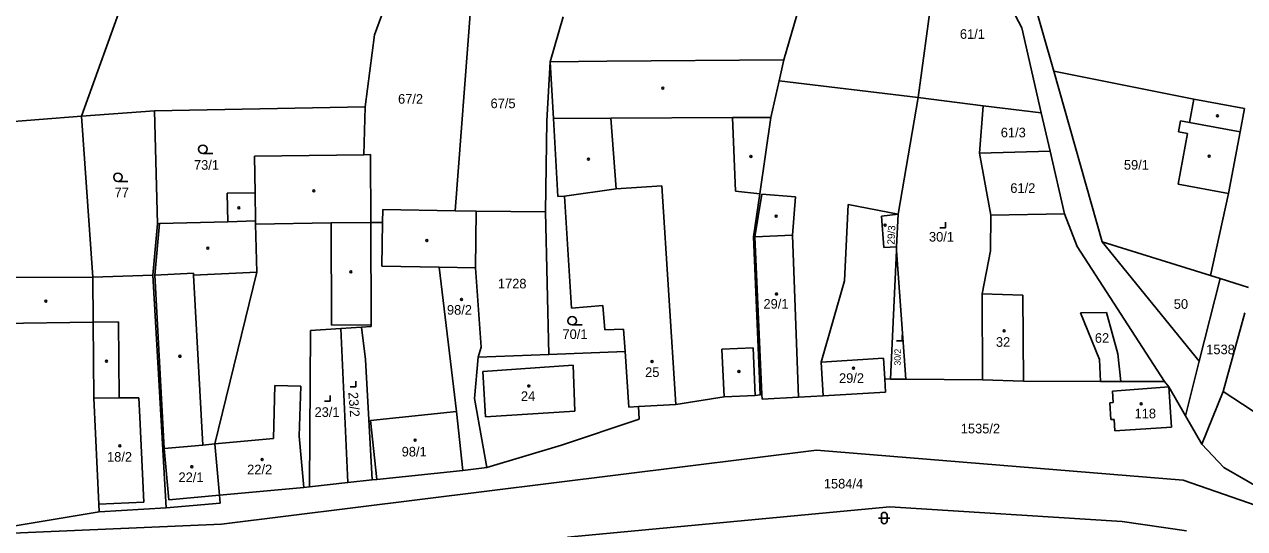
# Model space of a CAD drawing. Extents: x -801826 to -800592, y -1032871 to -1031813.
# Drawn here: x -801458.2 to -801242.3, y -1032295.9 to -1032206.7 of the extents above; entities that cross this region are included whole.
import ezdxf

# ---------------------------------------------------------------- set-up
doc = ezdxf.new("R2010")
doc.units = 0
for name, color, linetype in [('Vrstva 1', 7, 'Continuous'), ('Vrstva 18', 7, 'Continuous'), ('Vrstva 19', 7, 'Continuous'), ('Vrstva 25', 7, 'Continuous'), ('Vrstva 4', 7, 'Continuous')]:
    doc.layers.add(name, color=color, linetype=linetype)

msp = doc.modelspace()

# ---------------------------------------------------------------- linework, layer by layer
at = {"layer": 'Vrstva 1'}
for p, q in [((-801448.05, -1032222.93), (-801416.74, -1032135.73)), ((-801448.05, -1032222.93), (-801416.74, -1032135.73)), ((-801316.77, -1032188.79), (-801323.85, -1032212.97)), ((-801296.17, -1032190.86), (-801300.07, -1032219.68)), ((-801281.75, -1032207.34), (-801287.23, -1032196.91)), ((-801276.11, -1032214.97), (-801280.45, -1032199.73)), ((-801396.23, -1032208.59), (-801393.66, -1032201.6)), ((-801393.66, -1032201.6), (-801396.23, -1032208.59)), ((-801381.98, -1032239.7), (-801379.18, -1032203.38)), ((-801381.98, -1032239.7), (-801379.18, -1032203.38)), ((-801379.18, -1032203.38), (-801381.98, -1032239.7)), ((-801365.14, -1032213.36), (-801362.89, -1032205.37)), ((-801365.14, -1032213.36), (-801362.89, -1032205.37)), ((-801397.89, -1032221.33), (-801396.23, -1032208.59)), ((-801396.23, -1032208.59), (-801397.89, -1032221.33)), ((-801278.3, -1032222.36), (-801281.75, -1032207.34)), ((-801323.85, -1032212.97), (-801355.17, -1032213.25)), ((-801323.85, -1032212.97), (-801324.69, -1032216.69)), ((-801365.77, -1032223.78), (-801365.14, -1032213.36)), ((-801365.77, -1032223.78), (-801365.14, -1032213.36)), ((-801355.17, -1032213.25), (-801365.14, -1032213.36)), ((-801364.57, -1032223.37), (-801365.14, -1032213.36)), ((-801267.55, -1032245.2), (-801276.11, -1032214.97)), ((-801276.11, -1032214.97), (-801251.32, -1032219.94)), ((-801324.69, -1032216.69), (-801326.16, -1032223.18)), ((-801300.07, -1032219.68), (-801324.69, -1032216.69)), ((-801435.15, -1032222.03), (-801397.89, -1032221.33)), ((-801397.89, -1032221.33), (-801398.12, -1032229.78)), ((-801397.89, -1032221.33), (-801398.12, -1032229.78)), ((-801303.62, -1032240.3), (-801300.07, -1032219.68)), ((-801300.07, -1032219.68), (-801288.59, -1032221.1)), ((-801289.22, -1032229.47), (-801288.59, -1032221.1)), ((-801288.59, -1032221.1), (-801278.3, -1032222.36)), ((-801252.09, -1032224.07), (-801251.32, -1032219.94)), ((-801474.72, -1032225.02), (-801448.05, -1032222.93)), ((-801474.72, -1032225.02), (-801448.05, -1032222.93)), ((-801448.05, -1032222.93), (-801435.15, -1032222.03)), ((-801446.08, -1032251.42), (-801448.05, -1032222.93)), ((-801434.6, -1032241.97), (-801435.15, -1032222.03)), ((-801363.79, -1032237.15), (-801364.57, -1032223.37)), ((-801326.16, -1032223.18), (-801328.11, -1032236.71)), ((-801278.3, -1032222.36), (-801276.74, -1032229.12)), ((-801254.03, -1032225.74), (-801253.66, -1032223.77)), ((-801253.66, -1032223.77), (-801252.09, -1032224.07)), ((-801365.98, -1032239.9), (-801365.77, -1032223.78)), ((-801365.98, -1032239.9), (-801365.77, -1032223.78)), ((-801252.46, -1032226.03), (-801254.03, -1032225.74)), ((-801254.12, -1032234.98), (-801252.46, -1032226.03)), ((-801417.45, -1032230.02), (-801398.12, -1032229.78)), ((-801417.37, -1032236.53), (-801417.45, -1032230.02)), ((-801398.12, -1032229.78), (-801396.92, -1032229.76)), ((-801398.12, -1032229.78), (-801396.92, -1032229.76)), ((-801396.92, -1032229.76), (-801396.89, -1032241.78)), ((-801396.92, -1032229.76), (-801396.89, -1032241.78)), ((-801276.74, -1032229.12), (-801289.22, -1032229.47)), ((-801287.21, -1032240.47), (-801289.22, -1032229.47)), ((-801276.74, -1032229.12), (-801274.19, -1032240.25)), ((-801417.37, -1032236.53), (-801422.27, -1032236.59)), ((-801422.27, -1032236.59), (-801422.2, -1032241.63)), ((-801417.37, -1032236.53), (-801417.3, -1032241.49)), ((-801328.11, -1032236.71), (-801329.2, -1032244.28)), ((-801245.17, -1032236.64), (-801254.12, -1032234.98)), ((-801245.17, -1032236.64), (-801248.38, -1032251.15)), ((-801362.64, -1032237.08), (-801363.79, -1032237.15)), ((-801361.4, -1032256.92), (-801362.64, -1032237.08)), ((-801313.09, -1032252.05), (-801312.46, -1032238.57)), ((-801312.46, -1032238.57), (-801303.62, -1032240.3)), ((-801394.75, -1032239.44), (-801394.8, -1032241.77)), ((-801394.8, -1032241.77), (-801394.75, -1032239.44)), ((-801381.98, -1032239.7), (-801394.75, -1032239.44)), ((-801394.75, -1032239.44), (-801381.98, -1032239.7)), ((-801378.25, -1032239.77), (-801381.98, -1032239.7)), ((-801381.98, -1032239.7), (-801378.25, -1032239.77)), ((-801378.4, -1032249.79), (-801378.25, -1032239.77)), ((-801378.25, -1032239.77), (-801365.98, -1032239.9)), ((-801378.25, -1032239.77), (-801365.98, -1032239.9)), ((-801365.98, -1032239.9), (-801365.4, -1032265.08)), ((-801303.89, -1032246.07), (-801303.62, -1032240.3)), ((-801287.28, -1032246.76), (-801287.21, -1032240.47)), ((-801274.19, -1032240.25), (-801287.21, -1032240.47)), ((-801271.96, -1032246), (-801274.19, -1032240.25)), ((-801435.46, -1032251.09), (-801434.6, -1032241.97)), ((-801434.6, -1032241.97), (-801434.25, -1032241.96)), ((-801422.2, -1032241.63), (-801434.25, -1032241.96)), ((-801417.3, -1032241.49), (-801417.3, -1032242.04)), ((-801417.3, -1032242.04), (-801417.05, -1032250.54)), ((-801394.8, -1032241.77), (-801396.89, -1032241.78)), ((-801396.89, -1032241.78), (-801394.8, -1032241.77)), ((-801396.89, -1032241.78), (-801396.85, -1032259.87)), ((-801329.2, -1032244.28), (-801328, -1032272.21)), ((-801267.55, -1032245.2), (-801250.37, -1032266.27)), ((-801248.38, -1032251.15), (-801267.55, -1032245.2)), ((-801303.92, -1032246.72), (-801304.98, -1032269.44)), ((-801303.92, -1032246.72), (-801303.89, -1032246.07)), ((-801302.26, -1032269.46), (-801303.92, -1032246.72)), ((-801288.76, -1032254.36), (-801287.28, -1032246.76)), ((-801256.53, -1032269.9), (-801271.96, -1032246)), ((-801446.08, -1032251.42), (-801462.54, -1032251.48)), ((-801446.08, -1032251.42), (-801435.46, -1032251.09)), ((-801446.08, -1032251.42), (-801446.01, -1032259.36)), ((-801433.1, -1032292.23), (-801435.46, -1032251.09)), ((-801424.5, -1032280.92), (-801417.05, -1032250.54)), ((-801378.4, -1032249.79), (-801384.79, -1032249.68)), ((-801384.79, -1032249.68), (-801381.72, -1032275.18)), ((-801377.36, -1032263.81), (-801378.4, -1032249.79)), ((-801246.69, -1032251.67), (-801250.37, -1032266.27)), ((-801246.69, -1032251.67), (-801248.38, -1032251.15)), ((-801241.66, -1032253.23), (-801246.69, -1032251.67)), ((-801317.25, -1032266.46), (-801313.09, -1032252.05)), ((-801288.69, -1032269.58), (-801288.76, -1032254.36)), ((-801355.87, -1032256.41), (-801361.4, -1032256.92)), ((-801355.48, -1032260.74), (-801355.87, -1032256.41)), ((-801266.78, -1032257.67), (-801271.39, -1032257.72)), ((-801271.39, -1032257.72), (-801268.01, -1032266.01)), ((-801264.75, -1032265.01), (-801266.78, -1032257.67)), ((-801246.16, -1032271.65), (-801242.31, -1032257.72)), ((-801445.89, -1032272.81), (-801446.01, -1032259.36)), ((-801402.19, -1032260.49), (-801398.52, -1032260.27)), ((-801398.52, -1032260.27), (-801396.84, -1032260.13)), ((-801397.81, -1032265.98), (-801398.52, -1032260.27)), ((-801396.84, -1032260.13), (-801396.85, -1032259.87)), ((-801407.71, -1032288.51), (-801407.53, -1032260.84)), ((-801407.53, -1032260.84), (-801402.19, -1032260.49)), ((-801400.97, -1032287.76), (-801402.19, -1032260.49)), ((-801352.2, -1032260.61), (-801355.48, -1032260.74)), ((-801352.2, -1032260.61), (-801351.93, -1032264.58)), ((-801377.9, -1032265.55), (-801377.36, -1032263.81)), ((-801351.93, -1032264.58), (-801365.4, -1032265.08)), ((-801351.93, -1032264.58), (-801351.27, -1032274.41)), ((-801396.63, -1032287.28), (-801397.81, -1032265.98)), ((-801378.53, -1032272.86), (-801377.9, -1032265.55)), ((-801365.4, -1032265.08), (-801377.9, -1032265.55)), ((-801306.19, -1032265.76), (-801317.25, -1032266.46)), ((-801316.89, -1032272.41), (-801317.25, -1032266.46)), ((-801305.98, -1032269.43), (-801306.19, -1032265.76)), ((-801268.01, -1032266.01), (-801267.83, -1032269.86)), ((-801264.23, -1032269.88), (-801264.75, -1032265.01)), ((-801250.37, -1032266.27), (-801252.81, -1032275.94)), ((-801305.85, -1032271.76), (-801305.98, -1032269.43)), ((-801305.98, -1032269.43), (-801304.98, -1032269.44)), ((-801304.98, -1032269.44), (-801302.26, -1032269.46)), ((-801302.26, -1032269.46), (-801288.69, -1032269.58)), ((-801281.47, -1032269.82), (-801288.69, -1032269.58)), ((-801267.83, -1032269.86), (-801281.47, -1032269.82)), ((-801264.23, -1032269.88), (-801267.83, -1032269.86)), ((-801265.72, -1032271.58), (-801255.76, -1032270.84)), ((-801256.53, -1032269.9), (-801264.23, -1032269.88)), ((-801255.76, -1032270.84), (-801256.53, -1032269.9)), ((-801255.27, -1032277.97), (-801255.76, -1032270.84)), ((-801252.81, -1032275.94), (-801255.76, -1032270.84)), ((-801445, -1032291.59), (-801445.89, -1032272.81)), ((-801376.35, -1032285.06), (-801378.53, -1032272.86)), ((-801334.4, -1032272.57), (-801342.94, -1032273.94)), ((-801328.9, -1032272.32), (-801334.4, -1032272.57)), ((-801328.9, -1032272.32), (-801328, -1032272.21)), ((-801328, -1032272.21), (-801327.72, -1032272.18)), ((-801327.68, -1032272.98), (-801327.72, -1032272.18)), ((-801321.23, -1032272.63), (-801327.68, -1032272.98)), ((-801316.89, -1032272.41), (-801321.23, -1032272.63)), ((-801305.85, -1032271.76), (-801316.89, -1032272.41)), ((-801265.6, -1032273.58), (-801265.72, -1032271.58)), ((-801249.91, -1032280.96), (-801246.16, -1032271.65)), ((-801215.82, -1032291.6), (-801246.16, -1032271.65)), ((-801381.72, -1032275.18), (-801380.62, -1032285.59)), ((-801351.27, -1032274.41), (-801349.57, -1032274.31)), ((-801349.57, -1032274.31), (-801342.94, -1032273.94)), ((-801349.42, -1032276.55), (-801349.57, -1032274.31)), ((-801266.2, -1032273.62), (-801265.6, -1032273.58)), ((-801266.02, -1032276.62), (-801266.2, -1032273.62)), ((-801363.15, -1032281.14), (-801349.42, -1032276.55)), ((-801265.41, -1032276.59), (-801266.02, -1032276.62)), ((-801265.29, -1032278.59), (-801265.41, -1032276.59)), ((-801249.91, -1032280.96), (-801252.81, -1032275.94)), ((-801265.29, -1032278.59), (-801255.27, -1032277.97)), ((-801423.66, -1032289.99), (-801424.5, -1032280.92)), ((-801423.3, -1032295.08), (-801318.09, -1032281.99)), ((-801376.35, -1032285.06), (-801363.15, -1032281.14)), ((-801318.09, -1032281.99), (-801253.19, -1032287.31)), ((-801246.04, -1032285.11), (-801249.91, -1032280.96)), ((-801380.62, -1032285.59), (-801395.83, -1032287.2)), ((-801380.62, -1032285.59), (-801376.35, -1032285.06)), ((-801228.18, -1032295.28), (-801246.04, -1032285.11)), ((-801407.71, -1032288.51), (-801408.71, -1032288.6)), ((-801400.97, -1032287.76), (-801407.71, -1032288.51)), ((-801396.63, -1032287.28), (-801400.97, -1032287.76)), ((-801395.83, -1032287.2), (-801396.63, -1032287.28)), ((-801253.19, -1032287.31), (-801216.74, -1032299.98)), ((-801408.71, -1032288.6), (-801423.66, -1032289.99)), ((-801423.66, -1032289.99), (-801423.54, -1032291.4)), ((-801444.94, -1032292.94), (-801445, -1032291.59)), ((-801433.1, -1032292.23), (-801444.94, -1032292.94)), ((-801423.54, -1032291.4), (-801433.1, -1032292.23)), ((-801362.11, -1032297.43), (-801305.07, -1032292.01)), ((-801305.07, -1032292.01), (-801263.98, -1032294.66)), ((-801444.94, -1032292.94), (-801461.89, -1032295.77)), ((-801263.98, -1032294.66), (-801252.6, -1032296.27)), ((-801466.62, -1032296.97), (-801423.3, -1032295.08))]:
    msp.add_line(p, q, dxfattribs=at)
at = {"layer": 'Vrstva 25'}
for p, q in [((-801424.84, -1032229.56), (-801426.59, -1032229.56)), ((-801439.86, -1032234.51), (-801441.61, -1032234.51)), ((-801296.22, -1032242.69), (-801295.22, -1032242.69)), ((-801295.22, -1032242.69), (-801295.22, -1032241.69)), ((-801359.52, -1032259.88), (-801361.27, -1032259.88)), ((-801302.93, -1032262.68), (-801302.93, -1032261.68)), ((-801303.93, -1032262.68), (-801302.93, -1032262.68)), ((-801400.53, -1032270.83), (-801399.53, -1032270.83)), ((-801399.53, -1032270.83), (-801399.53, -1032269.83)), ((-801405.06, -1032273.36), (-801404.06, -1032273.36)), ((-801404.06, -1032273.36), (-801404.06, -1032272.36)), ((-801307.08, -1032294.02), (-801305.08, -1032294.02)), ((-801306.58, -1032294.52), (-801306.58, -1032293.52)), ((-801305.58, -1032294.52), (-801305.58, -1032293.52))]:
    msp.add_line(p, q, dxfattribs=at)
for centre, radius in [((-801345.26, -1032217.98), 0.175), ((-801247.15, -1032222.9), 0.175), ((-801426.59, -1032228.81), 0.75), ((-801329.65, -1032230.07), 0.175), ((-801248.61, -1032230.02), 0.175), ((-801358.4, -1032230.54), 0.175), ((-801441.61, -1032233.76), 0.75), ((-801406.98, -1032236.18), 0.175), ((-801420.22, -1032239.15), 0.175), ((-801325.2, -1032240.65), 0.175), ((-801305.94, -1032242.22), 0.175), ((-801386.98, -1032244.95), 0.175), ((-801425.72, -1032246.29), 0.175), ((-801400.41, -1032250.5), 0.175), ((-801454.35, -1032255.65), 0.175), ((-801380.83, -1032255.36), 0.175), ((-801325.14, -1032254.4), 0.175), ((-801361.27, -1032259.13), 0.75), ((-801284.89, -1032260.91), 0.175), ((-801443.64, -1032266.26), 0.175), ((-801430.64, -1032265.42), 0.175), ((-801347.15, -1032266.34), 0.175), ((-801331.77, -1032268.1), 0.175), ((-801311.52, -1032267.51), 0.175), ((-801368.96, -1032270.67), 0.175), ((-801260.62, -1032273.81), 0.175), ((-801441.28, -1032281.24), 0.175), ((-801389.06, -1032280.23), 0.175), ((-801416.11, -1032283.68), 0.175), ((-801428.55, -1032284.94), 0.175)]:
    msp.add_circle(centre, radius, dxfattribs=at)
for centre, start, end in [((-801306.08, -1032293.52), 0, 180), ((-801306.08, -1032294.52), 180, 0)]:
    msp.add_arc(centre, 0.5, start, end, dxfattribs=at)
at = {"layer": 'Vrstva 4'}
for p, q in [((-801251.32, -1032219.94), (-801242.38, -1032221.6)), ((-801242.38, -1032221.6), (-801243.14, -1032225.73)), ((-801354.41, -1032223.32), (-801364.57, -1032223.37)), ((-801354.41, -1032223.32), (-801332.91, -1032223.21)), ((-801353.51, -1032235.79), (-801354.41, -1032223.32)), ((-801332.91, -1032223.21), (-801326.16, -1032223.18)), ((-801332.91, -1032223.21), (-801332.38, -1032236.24)), ((-801243.14, -1032225.73), (-801252.09, -1032224.07)), ((-801243.14, -1032225.73), (-801245.17, -1032236.64)), ((-801353.51, -1032235.79), (-801362.64, -1032237.08)), ((-801345.43, -1032235.27), (-801353.51, -1032235.79)), ((-801342.94, -1032273.94), (-801345.43, -1032235.27)), ((-801332.38, -1032236.24), (-801328.11, -1032236.71)), ((-801328.95, -1032244.27), (-801327.71, -1032236.75)), ((-801327.71, -1032236.75), (-801321.77, -1032237.23)), ((-801322.31, -1032244), (-801321.77, -1032237.23)), ((-801303.62, -1032240.3), (-801306.56, -1032240.63)), ((-801306.56, -1032240.63), (-801306.18, -1032246.15)), ((-801435.11, -1032251.08), (-801434.25, -1032241.96)), ((-801422.2, -1032241.63), (-801417.3, -1032241.49)), ((-801403.91, -1032241.8), (-801417.3, -1032242.04)), ((-801396.89, -1032241.78), (-801403.91, -1032241.8)), ((-801403.91, -1032241.8), (-801403.86, -1032259.89)), ((-801394.95, -1032249.5), (-801394.8, -1032241.77)), ((-801328.95, -1032244.27), (-801322.31, -1032244)), ((-801327.72, -1032272.18), (-801328.95, -1032244.27)), ((-801321.23, -1032272.63), (-801322.31, -1032244)), ((-801306.18, -1032246.15), (-801303.89, -1032246.07)), ((-801384.79, -1032249.68), (-801394.95, -1032249.5)), ((-801428.27, -1032250.7), (-801435.11, -1032251.08)), ((-801433.44, -1032281.75), (-801435.11, -1032251.08)), ((-801428.26, -1032251.05), (-801428.27, -1032250.7)), ((-801417.05, -1032250.54), (-801428.26, -1032251.05)), ((-801426.6, -1032281.11), (-801428.26, -1032251.05)), ((-801288.76, -1032254.36), (-801281.54, -1032254.59)), ((-801281.47, -1032269.82), (-801281.54, -1032254.59)), ((-801462.46, -1032259.63), (-801446.01, -1032259.36)), ((-801441.53, -1032259.32), (-801446.01, -1032259.36)), ((-801441.41, -1032272.77), (-801441.53, -1032259.32)), ((-801403.86, -1032259.89), (-801396.85, -1032259.87)), ((-801329.28, -1032263.9), (-801334.78, -1032264.15)), ((-801334.4, -1032272.57), (-801334.78, -1032264.15)), ((-801328.9, -1032272.32), (-801329.28, -1032263.9)), ((-801377.08, -1032268.12), (-801361.1, -1032267.01)), ((-801376.58, -1032276.15), (-801377.08, -1032268.12)), ((-801360.8, -1032275.12), (-801361.1, -1032267.01)), ((-801414.09, -1032279.95), (-801413.85, -1032270.57)), ((-801413.85, -1032270.57), (-801409.27, -1032270.68)), ((-801409.27, -1032270.68), (-801409.55, -1032279.53)), ((-801441.41, -1032272.77), (-801445.89, -1032272.81)), ((-801440.41, -1032272.76), (-801441.41, -1032272.77)), ((-801437.9, -1032272.74), (-801440.41, -1032272.76)), ((-801437.74, -1032276.17), (-801437.9, -1032272.74)), ((-801396.93, -1032276.79), (-801381.72, -1032275.18)), ((-801360.8, -1032275.12), (-801376.58, -1032276.15)), ((-801437.03, -1032291.22), (-801437.74, -1032276.17)), ((-801395.83, -1032287.2), (-801396.93, -1032276.79)), ((-801408.71, -1032288.6), (-801409.55, -1032279.53)), ((-801426.6, -1032281.11), (-801433.44, -1032281.75)), ((-801432.6, -1032290.82), (-801433.44, -1032281.75)), ((-801424.5, -1032280.92), (-801426.6, -1032281.11)), ((-801414.09, -1032279.95), (-801424.5, -1032280.92)), ((-801432.6, -1032290.82), (-801423.66, -1032289.99)), ((-801437.03, -1032291.22), (-801445, -1032291.59))]:
    msp.add_line(p, q, dxfattribs=at)

# ---------------------------------------------------------------- texts
at = {"layer": 'Vrstva 18'}
for s, p in [('61/1', (-801292.7, -1032209.28)), ('67/2', (-801392.07, -1032220.75)), ('67/5', (-801375.71, -1032221.54)), ('61/3', (-801285.47, -1032226.69)), ('73/1', (-801428.16, -1032232.43)), ('59/1', (-801263.69, -1032232.41)), ('77', (-801442.2, -1032237.28)), ('61/2', (-801283.78, -1032236.52)), ('1728', (-801374.41, -1032253.41)), ('50', (-801254.87, -1032257.02)), ('70/1', (-801362.99, -1032262.36)), ('62', (-801268.83, -1032263.03)), ('1538', (-801249.13, -1032265.05)), ('1535/2', (-801292.54, -1032279.05)), ('1584/4', (-801316.76, -1032288.79))]:
    msp.add_text(s, height=1.7, dxfattribs=at).set_placement(p)
at = {"layer": 'Vrstva 19'}
for s, height, rotation, p in [('29/3', 1.3, 87.3246, (-801304.26, -1032245.68)), ('30/2', 1.14, 89.0833, (-801303.17, -1032267.06)), ('23/2', 1.7, 274.3756, (-801400.87, -1032271.8))]:
    msp.add_text(s, height=height, rotation=rotation, dxfattribs=at).set_placement(p)
for s, p in [('30/1', (-801298.17, -1032245.13)), ('29/1', (-801327.44, -1032256.99)), ('98/2', (-801383.42, -1032258.06)), ('32', (-801286.33, -1032263.74)), ('25', (-801348.37, -1032269.08)), ('29/2', (-801314.08, -1032270.12)), ('24', (-801370.34, -1032273.31)), ('23/1', (-801406.84, -1032276.13)), ('118', (-801261.8, -1032276.38)), ('98/1', (-801391.43, -1032283.13)), ('18/2', (-801443.54, -1032284.05)), ('22/1', (-801430.9, -1032287.66)), ('22/2', (-801418.76, -1032286.28))]:
    msp.add_text(s, height=1.7, dxfattribs=at).set_placement(p)

doc.saveas('drawing.dxf')
